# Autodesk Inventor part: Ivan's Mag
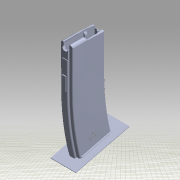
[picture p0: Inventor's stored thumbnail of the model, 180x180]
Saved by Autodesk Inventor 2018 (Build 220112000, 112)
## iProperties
Created: 2018-11
Part Number: Ivan's Mag
Material: Generic
Description: STEP AP214
Document SubType Name: Modeling
Designer: johne
Appearance: Default
Sending System: Autodesk Inventor 2018
Preprocessor: ST-DEVELOPER v16.13
Title: D:\doodoo.stp
Author: johne
Revision Number: ANY
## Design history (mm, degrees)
feature "Solid1" [Base]
sketch "Sketch1"
  geometry: L1 (33.267, 81.349)-(-14.403, 81.349); L2 (-14.403, 81.349)-(-14.403, -22.431); L3 (-14.403, -22.431)-(33.267, -22.431); L4 (33.267, -22.431)-(33.267, 81.349); 1 further point
  constraints: 8 end point, 2 parallel, 1 horizontal, 1 perpendicular
sketch "Sketch2"
  geometry: L1 (18.644, 14.088)-(16.699, 14.088) reference; L2 (17.921, 14.088)-(19.094, 14.088); L3 (19.094, 14.088)-(19.094, 16.078); L4 (19.094, 16.078)-(17.921, 16.078); L5 (17.921, 16.078)-(17.921, 14.088); 1 further point
  constraints: 8 end point, 2 parallel, 1 horizontal, 1 perpendicular, 1 point on line
extrude "Extrusion1" join sketch "Sketch2" distance "d0" = 1; taper "d1" = 0 deg
workplane "Work Plane1"
mirror "Mirror1"
extrude "Extrusion2" join sketch "Sketch1" distance "d2" = 1; taper "d3" = 0 deg
workplane "Work Plane2"
sketch "Sketch5"
  geometry: L1 (2.603, 72.72)-(2.603, 66.43); L2 (0.279, 72.72)-(0.279, 66.179); L3 (0.279, 72.72)-(2.603, 72.72); L4 (15.967, 66.167)-(15.939, 72.72) reference; L5 (15.939, 72.72)-(18.263, 72.72) reference; L6 (18.263, 66.179)-(18.263, 72.72) reference; L7 (0.279, 72.415)-(0.279, 0.305) reference; L8 (0.279, 66.336)-(0.279, 66.179); L9 (2.575, 66.167)-(2.575, 66.167); L10 (2.603, 66.43)-(2.603, 72.72); L11 (2.603, 72.72)-(0.279, 72.72); L12 (2.603, 72.72)-(0.279, 72.72) reference; L13 (0.279, 70.521)-(0.279, 72.72); L14 (0.279, 72.72)-(0.279, 72.72); L15 (2.603, 66.43)-(2.603, 72.72); L16 (2.603, 72.72)-(0.279, 72.72); A1 r 4.763 centre (5.042, 70.521) between (2.733, 74.687) and (0.279, 70.521); A2 r 4.763 centre (5.042, 70.521) between (2.126, 74.287) and (2.603, 66.43); 6 further points; 3 other entities
  constraints: 18 end point, 3 collinear, 3 point on circle, 2 centre point, 1 perpendicular, 1 point on line, 1 vertical, 8 other
extrude "Extrusion3" cut sketch "Sketch5" distance "d5" = 10; taper "d6" = 0 deg
fillet "Fillet1" dims "d7" = 7
sketch "Sketch6"
  geometry: L1 (-2.603, 72.72)-(-2.575, 66.118) reference; L2 (-2.575, 66.118)-(-2.078, 66.118) reference; L3 (-0.279, 72.72)-(-0.279, 70.521) reference; L4 (-2.603, 72.72)-(-0.279, 72.72) reference; A1 r 7 centre (4.436, 63.556) between (-1.204, 67.701) and (-2.078, 66.118) reference; A2 r 4.763 centre (-5.042, 70.521) between (-1.204, 67.701) and (-0.279, 70.521) reference; 1 further point
extrude "Extrusion4" cut sketch "Sketch6" distance "d8" = 0.1; taper "d9" = 0 deg
mirror "Mirror2"
mirror "Mirror3"
sketch "Sketch7"
  geometry: L1 (25.873, -80.313)-(53.423, -80.313); L2 (53.423, -80.313)-(53.423, -100.796); L3 (53.423, -100.796)-(25.873, -100.796); L4 (25.873, -100.796)-(25.873, -80.313); 1 further point
  constraints: 8 end point, 2 parallel, 1 horizontal, 1 perpendicular
extrude "Extrusion5" cut sketch "Sketch7" distance "d10" = 10; taper "d11" = 0 deg
mirror "Mirror4"
sketch "Sketch8"
  geometry: L1 (0.704, 1.402)-(0.704, 0.166) reference; L2 (0.704, 1.402)-(0, 1.402) reference; L3 (0, 0)-(0, 1.402) reference; L4 (-1.125, -0.104)-(-0.453, -0.012) reference; 4 further points
  constraints: 5 other
extrude "Extrusion6" join sketch "Sketch8" stored distance "d12" = 10; taper "d13" = 0 deg
sketch "Sketch9"
  geometry: L1 (55.169, -2.227)-(55.169, -2.532) reference; L2 (-13.397, -2.227)-(-13.397, 0.051); L3 (-13.397, 0.051)-(55.169, 0.051); L4 (55.169, 0.051)-(55.169, -2.227); L5 (29.193, 0)-(28.489, 0); L6 (28.489, 0)-(0, 0); L7 (1.575, -2.227)-(0, 0); L8 (27.924, -2.227)-(1.575, -2.227); L9 (55.169, -2.227)-(28.627, -2.227) reference; L10 (27.924, -2.227)-(28.627, -2.227); 3 further points
  constraints: 8 end point, 1 horizontal, 1 parallel, 8 other
extrude "Extrusion7" cut sketch "Sketch9" stored distance "d14" = 10; taper "d15" = 0 deg
feature "Base2"
mirror "Mirror5"
body "Solid2"
node "Projected Loop2"
node "Projected Loop4"
node "Projected Loop5"
body "Solid3"
other parameters: "d4" = -14.56
